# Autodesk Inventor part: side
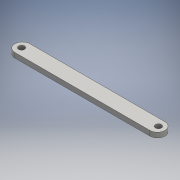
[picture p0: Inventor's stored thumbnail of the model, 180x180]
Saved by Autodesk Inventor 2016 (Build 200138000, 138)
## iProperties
Created: 2016-02
Part Number: side
Material: Generic
Document SubType Name: Modeling
Designer: Juha-Pekka
Density: 1 g/cm^3
Appearance: Default
Author: Juha-Pekka
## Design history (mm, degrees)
sketch "Sketch1"
  geometry: L1 (142.414, 15)-(7.345, 15); L2 (0, 9.015)-(0, 5.985); L3 (7.345, 0)-(142.414, 0); A1 r 7.5 centre (7.345, 7.5) between (7.345, 15) and (0, 5.985); A2 r 7.5 centre (7.345, 7.5) between (0, 5.985) and (7.345, 0); A3 r 7.5 centre (142.414, 7.5) between (142.414, 0) and (142.414, 15); 1 further point
  constraints: 7 point on circle, 6 end point, 3 centre point, 1 horizontal, 1 parallel, 1 tangent
extrude "Extrusion1" new body sketch "Sketch1" distance "d3" = 5; taper "d4" = 0 deg
hole "Hole1" diameter "d7" = 6; stored, may be unused: countersink angle "d11" = 90 deg, drill point angle "d13" = 118 deg; dims "d5" = 10, "d6" = 10, "d8" = 6, "d9" = 4, "d10" = 2, "d12" = 8
hole "Hole2" diameter "d16" = 6; stored, may be unused: countersink angle "d20" = 90 deg, drill point angle "d22" = 118 deg; dims "d14" = 10, "d15" = 10, "d17" = 6, "d18" = 4, "d19" = 2, "d21" = 8
body "Solid1"
